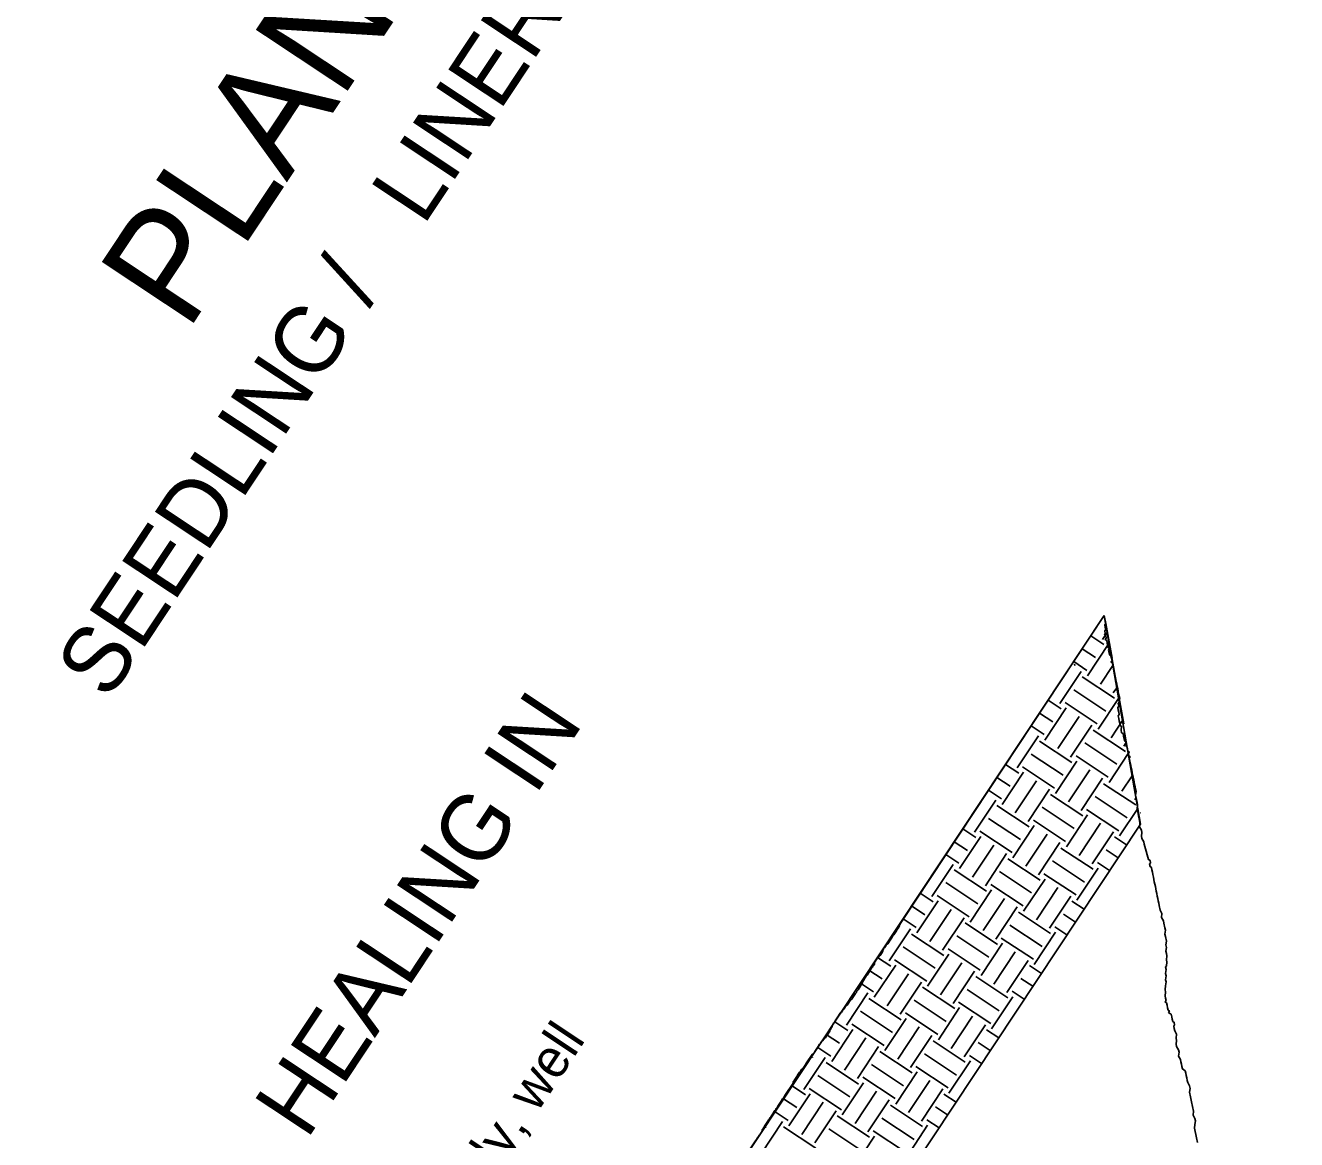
# Model space of a CAD drawing. Extents: x 561231 to 564240, y 590260 to 602519.
# Drawn here: x 563343 to 563465.5, y 590700.8 to 590808.3 of the extents above; entities that cross this region are included whole.
import ezdxf

# ---------------------------------------------------------------- set-up
doc = ezdxf.new("R2010")
doc.units = 0
doc.layers.add('Old_Level_1', color=7, linetype='Continuous')

msp = doc.modelspace()

# ---------------------------------------------------------------- linework, layer by layer
at = {"layer": 'Old_Level_1'}
for p, q in [((563410.25, 590696), (563446.98, 590751.37)), ((563446.98, 590751.37), (563448.88, 590740.92)), ((563446.98, 590751.37), (563450.47, 590731.26)), ((563447.12, 590750.62), (563447.73, 590747.26)), ((563445.68, 590749.42), (563446.95, 590748.57)), ((563446.81, 590749.08), (563447.26, 590749.75)), ((563444.86, 590748.18), (563446.13, 590747.33)), ((563445.37, 590745.57), (563447.43, 590748.67)), ((563447.33, 590749.18), (563447.36, 590749.16)), ((563444.04, 590746.94), (563445.31, 590746.09)), ((563442.7, 590742.88), (563444.75, 590745.98)), ((563444.17, 590746.57), (563444.09, 590746.7)), ((563446.61, 590744.75), (563447.81, 590746.55)), ((563444.86, 590745.46), (563447.96, 590743.41)), ((563444.04, 590744.22), (563447.14, 590742.17)), ((563446.4, 590740.43), (563448.36, 590743.39)), ((563447.85, 590743.92), (563448.18, 590744.42)), ((563441.26, 590739.37), (563443.32, 590742.47)), ((563441.57, 590743.21), (563442.84, 590742.37)), ((563443.21, 590742.98), (563446.31, 590740.93)), ((563440.75, 590741.97), (563442.02, 590741.13)), ((563442.5, 590738.54), (563444.56, 590741.65)), ((563443.74, 590737.72), (563445.8, 590740.82)), ((563447.64, 590739.6), (563448.73, 590741.26)), ((563438.58, 590736.68), (563440.64, 590739.78)), ((563439.92, 590740.73), (563441.19, 590739.89)), ((563445.92, 590740.33), (563449.02, 590738.27)), ((563440.75, 590739.26), (563443.85, 590737.21)), ((563445.1, 590739.09), (563448.2, 590737.03)), ((563448.88, 590738.78), (563449.1, 590739.12)), ((563439.92, 590738.02), (563443.02, 590735.97)), ((563442.28, 590734.23), (563444.34, 590737.33)), ((563444.27, 590737.85), (563447.37, 590735.79)), ((563447.44, 590735.27), (563449.29, 590738.06)), ((563437.15, 590733.17), (563439.21, 590736.27)), ((563437.46, 590737.01), (563438.73, 590736.17)), ((563439.1, 590736.78), (563442.2, 590734.73)), ((563443.52, 590733.4), (563445.58, 590736.5)), ((563448.68, 590734.45), (563449.66, 590735.92)), ((563436.63, 590735.77), (563437.9, 590734.93)), ((563438.39, 590732.34), (563440.45, 590735.44)), ((563444.76, 590732.58), (563446.82, 590735.68)), ((563446.92, 590735.16), (563450.03, 590733.11)), ((563434.47, 590730.48), (563436.53, 590733.58)), ((563435.81, 590734.53), (563437.08, 590733.69)), ((563439.63, 590731.52), (563441.69, 590734.62)), ((563441.8, 590734.13), (563444.91, 590732.07)), ((563446.1, 590733.92), (563449.2, 590731.87)), ((563449.92, 590733.62), (563450.03, 590733.79)), ((563436.63, 590733.06), (563439.73, 590731.01)), ((563440.98, 590732.89), (563444.08, 590730.83)), ((563445.28, 590732.68), (563448.38, 590730.63)), ((563448.46, 590730.13), (563450.21, 590732.76)), ((563450.45, 590732.35), (563450.47, 590732.34)), ((563450.47, 590731.26), (563421.94, 590688.25)), ((563435.81, 590731.82), (563438.91, 590729.77)), ((563438.17, 590728.02), (563440.23, 590731.12)), ((563440.16, 590731.65), (563443.26, 590729.59)), ((563443.33, 590729.07), (563445.38, 590732.17)), ((563444.57, 590728.25), (563446.62, 590731.35)), ((563433.04, 590726.97), (563435.09, 590730.07)), ((563433.34, 590730.81), (563434.61, 590729.97)), ((563434.99, 590730.58), (563438.09, 590728.53)), ((563439.41, 590727.2), (563441.47, 590730.3)), ((563445.81, 590727.42), (563447.86, 590730.52)), ((563447.98, 590730.03), (563449.14, 590729.26)), ((563432.52, 590729.57), (563433.79, 590728.73)), ((563434.28, 590726.14), (563436.33, 590729.24)), ((563440.65, 590726.38), (563442.71, 590729.48)), ((563442.81, 590728.96), (563445.91, 590726.91)), ((563447.16, 590728.79), (563448.32, 590728.02)), ((563430.36, 590724.28), (563432.42, 590727.38)), ((563431.7, 590728.33), (563432.97, 590727.49)), ((563435.52, 590725.32), (563437.57, 590728.42)), ((563437.69, 590727.93), (563440.79, 590725.87)), ((563441.99, 590727.72), (563445.09, 590725.67)), ((563446.34, 590727.55), (563447.5, 590726.78)), ((563432.52, 590726.86), (563435.62, 590724.81)), ((563436.87, 590726.69), (563439.97, 590724.63)), ((563441.17, 590726.48), (563444.27, 590724.43)), ((563444.35, 590723.93), (563446.41, 590727.03)), ((563431.7, 590725.62), (563434.8, 590723.57)), ((563434.06, 590721.82), (563436.11, 590724.92)), ((563436.05, 590725.45), (563439.15, 590723.39)), ((563439.21, 590722.87), (563441.27, 590725.97)), ((563440.45, 590722.04), (563442.51, 590725.14)), ((563428.92, 590720.77), (563430.98, 590723.87)), ((563429.23, 590724.61), (563430.5, 590723.77)), ((563430.87, 590724.38), (563433.97, 590722.33)), ((563435.3, 590721), (563437.35, 590724.1)), ((563441.69, 590721.22), (563443.75, 590724.32)), ((563443.87, 590723.83), (563445.03, 590723.06)), ((563428.41, 590723.37), (563429.68, 590722.53)), ((563430.16, 590719.94), (563432.22, 590723.04)), ((563436.54, 590720.18), (563438.59, 590723.28)), ((563438.7, 590722.76), (563441.8, 590720.71)), ((563443.05, 590722.59), (563444.21, 590721.82)), ((563427.58, 590722.13), (563428.85, 590721.29)), ((563431.4, 590719.12), (563433.46, 590722.22)), ((563433.58, 590721.73), (563436.68, 590719.67)), ((563437.88, 590721.52), (563440.98, 590719.47)), ((563442.23, 590721.35), (563443.39, 590720.58)), ((563426.25, 590718.08), (563428.3, 590721.18)), ((563428.41, 590720.66), (563431.51, 590718.6)), ((563432.76, 590720.49), (563435.86, 590718.43)), ((563437.05, 590720.28), (563440.15, 590718.23)), ((563440.24, 590717.72), (563442.29, 590720.83)), ((563427.58, 590719.42), (563430.68, 590717.36)), ((563431.93, 590719.25), (563435.03, 590717.19)), ((563435.1, 590716.67), (563437.16, 590719.77)), ((563436.34, 590715.84), (563438.4, 590718.94)), ((563424.81, 590714.56), (563426.87, 590717.66)), ((563425.12, 590718.41), (563426.39, 590717.57)), ((563426.76, 590718.18), (563429.86, 590716.12)), ((563429.94, 590715.62), (563432, 590718.72)), ((563431.18, 590714.8), (563433.24, 590717.9)), ((563437.58, 590715.02), (563439.64, 590718.12)), ((563439.76, 590717.63), (563440.92, 590716.86)), ((563424.29, 590717.17), (563425.56, 590716.33)), ((563426.05, 590713.74), (563428.11, 590716.84)), ((563432.42, 590713.98), (563434.48, 590717.08)), ((563434.59, 590716.56), (563437.69, 590714.51)), ((563438.93, 590716.39), (563440.1, 590715.62)), ((563423.47, 590715.93), (563424.74, 590715.09)), ((563427.29, 590712.92), (563429.35, 590716.02)), ((563429.47, 590715.53), (563432.57, 590713.47)), ((563433.76, 590715.32), (563436.86, 590713.27)), ((563438.11, 590715.15), (563439.27, 590714.38)), ((563422.13, 590711.88), (563424.19, 590714.98)), ((563424.29, 590714.46), (563427.39, 590712.4)), ((563428.64, 590714.29), (563431.74, 590712.23)), ((563432.94, 590714.08), (563436.04, 590712.03)), ((563436.12, 590711.52), (563438.18, 590714.62)), ((563423.47, 590713.22), (563426.57, 590711.16)), ((563427.82, 590713.05), (563430.92, 590710.99)), ((563430.99, 590710.47), (563433.04, 590713.57)), ((563432.23, 590709.64), (563434.28, 590712.74)), ((563420.7, 590708.36), (563422.75, 590711.46)), ((563421, 590712.21), (563422.27, 590711.37)), ((563422.65, 590711.98), (563425.75, 590709.92)), ((563425.83, 590709.42), (563427.89, 590712.52)), ((563427.07, 590708.6), (563429.13, 590711.7)), ((563433.47, 590708.82), (563435.52, 590711.92)), ((563435.64, 590711.43), (563436.81, 590710.66)), ((563420.18, 590710.97), (563421.45, 590710.13)), ((563421.94, 590707.54), (563423.99, 590710.64)), ((563428.31, 590707.78), (563430.37, 590710.88)), ((563430.47, 590710.36), (563433.57, 590708.3)), ((563434.82, 590710.19), (563435.98, 590709.42)), ((563419.36, 590709.73), (563420.63, 590708.89)), ((563423.18, 590706.72), (563425.23, 590709.82)), ((563425.35, 590709.33), (563428.45, 590707.27)), ((563429.65, 590709.12), (563432.75, 590707.06)), ((563434, 590708.95), (563435.16, 590708.18)), ((563418.02, 590705.67), (563420.08, 590708.77)), ((563418.86, 590708.73), (563418.85, 590708.75)), ((563420.18, 590708.26), (563423.28, 590706.2)), ((563424.53, 590708.09), (563427.63, 590706.03)), ((563428.83, 590707.88), (563431.93, 590705.82)), ((563432.01, 590705.32), (563434.07, 590708.42)), ((563419.36, 590707.02), (563422.46, 590704.96)), ((563423.71, 590706.85), (563426.81, 590704.79)), ((563426.87, 590704.26), (563428.93, 590707.37)), ((563428.11, 590703.44), (563430.17, 590706.54)), ((563416.58, 590702.16), (563418.64, 590705.26)), ((563416.89, 590706.01), (563418.16, 590705.17)), ((563418.53, 590705.78), (563421.64, 590703.72)), ((563421.72, 590703.22), (563423.77, 590706.32)), ((563422.96, 590702.4), (563425.01, 590705.5)), ((563429.36, 590702.62), (563431.41, 590705.72)), ((563416.07, 590704.77), (563417.34, 590703.93)), ((563417.82, 590701.34), (563419.88, 590704.44)), ((563424.2, 590701.58), (563426.25, 590704.68)), ((563426.36, 590704.16), (563429.46, 590702.1)), ((563431.53, 590705.23), (563432.69, 590704.46)), ((563415.24, 590703.53), (563416.51, 590702.69)), ((563419.06, 590700.52), (563421.12, 590703.62)), ((563421.24, 590703.13), (563424.34, 590701.07)), ((563425.54, 590702.92), (563428.64, 590700.86)), ((563430.71, 590703.99), (563431.87, 590703.22)), ((563413.91, 590699.47), (563415.96, 590702.57)), ((563414.36, 590701.96), (563414.32, 590702.03)), ((563416.07, 590702.06), (563419.17, 590700)), ((563420.42, 590701.89), (563423.52, 590699.83)), ((563424.71, 590701.68), (563427.81, 590699.62)), ((563427.9, 590699.12), (563429.95, 590702.22)), ((563429.89, 590702.75), (563431.05, 590701.98)), ((563422.76, 590698.06), (563424.82, 590701.16))]:
    msp.add_line(p, q, dxfattribs=at)
for points in [[(563446.98, 590751.37), (563427.44, 590721.83), (563427.37, 590721.73), (563427.27, 590721.58), (563427.25, 590721.44), (563427.19, 590721.34), (563427.12, 590721.24), (563427.02, 590721.09), (563426.95, 590720.98), (563426.88, 590720.88), (563426.81, 590720.78), (563426.75, 590720.68), (563426.68, 590720.58), (563426.61, 590720.48), (563426.54, 590720.37), (563426.48, 590720.27), (563426.41, 590720.17), (563426.34, 590720.07), (563426.27, 590719.97), (563426.2, 590719.86), (563426.1, 590719.71), (563425.98, 590719.64), (563425.92, 590719.54), (563425.85, 590719.44), (563425.78, 590719.34), (563425.71, 590719.23), (563425.65, 590719.13), (563425.63, 590719), (563425.56, 590718.89), (563425.49, 590718.79), (563425.43, 590718.69), (563425.36, 590718.59), (563425.29, 590718.49), (563425.17, 590718.42), (563425.1, 590718.32), (563425.04, 590718.21), (563424.97, 590718.11), (563424.9, 590718.01), (563424.83, 590717.91), (563424.82, 590717.77), (563424.75, 590717.67), (563424.68, 590717.57), (563424.62, 590717.47), (563424.55, 590717.36), (563424.48, 590717.26), (563424.41, 590717.16), (563424.34, 590717.06), (563424.28, 590716.96), (563424.18, 590716.8), (563424.11, 590716.7), (563424.04, 590716.6), (563423.97, 590716.5), (563423.9, 590716.4), (563423.84, 590716.29), (563423.77, 590716.19), (563423.7, 590716.09), (563423.68, 590715.95), (563423.62, 590715.85), (563423.55, 590715.75), (563423.48, 590715.65), (563423.41, 590715.55), (563423.35, 590715.44), (563423.25, 590715.29), (563423.14, 590715.14), (563423.08, 590715.04), (563423.01, 590714.93), (563422.94, 590714.83), (563422.87, 590714.73), (563422.81, 590714.63), (563422.74, 590714.53), (563422.67, 590714.42), (563422.52, 590714.3), (563422.42, 590714.15), (563422.32, 590714), (563422.25, 590713.9), (563422.18, 590713.79), (563422.06, 590713.73), (563421.99, 590713.62), (563421.93, 590713.52), (563421.86, 590713.42), (563421.79, 590713.32), (563421.72, 590713.22), (563421.65, 590713.11), (563421.54, 590713.05), (563421.43, 590712.89), (563421.37, 590712.79), (563421.3, 590712.69), (563421.23, 590712.59), (563421.16, 590712.49), (563421.1, 590712.38), (563421.03, 590712.28), (563420.96, 590712.18), (563420.89, 590712.08), (563420.83, 590711.98), (563420.76, 590711.87), (563420.74, 590711.74), (563420.67, 590711.64), (563420.61, 590711.53), (563420.54, 590711.43), (563420.52, 590711.3), (563420.45, 590711.19)], [(563446.98, 590751.37), (563447.12, 590750.62), (563447.03, 590750.48), (563447.07, 590750.25), (563447.12, 590750.02), (563447.03, 590749.89), (563447.08, 590749.66), (563446.99, 590749.52), (563447.12, 590749.43), (563447.17, 590749.2), (563447.08, 590749.06), (563447.22, 590748.97), (563447.26, 590748.74), (563447.31, 590748.51), (563447.35, 590748.28), (563447.49, 590748.19), (563447.4, 590748.05), (563447.45, 590747.82), (563447.49, 590747.6), (563447.63, 590747.5), (563447.68, 590747.27), (563447.73, 590747.05), (563447.63, 590746.91), (563447.77, 590746.82), (563447.82, 590746.59), (563447.86, 590746.36), (563447.91, 590746.13), (563447.96, 590745.9), (563448, 590745.67), (563448.05, 590745.44), (563448.1, 590745.21), (563448.14, 590744.98), (563448.19, 590744.76), (563448.24, 590744.53), (563448.28, 590744.3), (563448.33, 590744.07), (563448.37, 590743.84), (563448.42, 590743.61), (563448.47, 590743.38), (563448.38, 590743.24), (563448.42, 590743.01), (563448.33, 590742.88), (563448.38, 590742.65), (563448.29, 590742.51), (563448.33, 590742.28), (563448.38, 590742.05), (563448.43, 590741.82), (563448.33, 590741.69), (563448.38, 590741.46), (563448.43, 590741.23), (563448.47, 590741), (563448.52, 590740.77), (563448.66, 590740.68), (563448.61, 590740.31), (563448.66, 590740.08), (563448.8, 590739.99), (563448.84, 590739.76), (563448.89, 590739.53), (563448.94, 590739.3), (563449.07, 590739.21), (563449.12, 590738.98), (563449.03, 590738.85), (563449.17, 590738.76), (563449.21, 590738.53), (563449.26, 590738.3), (563449.4, 590738.21), (563449.31, 590738.07), (563449.35, 590737.84), (563449.49, 590737.75), (563449.4, 590737.61), (563449.45, 590737.38), (563449.49, 590737.15), (563449.54, 590736.92), (563449.59, 590736.69), (563449.63, 590736.46), (563449.68, 590736.24), (563449.72, 590736.01), (563449.77, 590735.78), (563449.82, 590735.55), (563449.91, 590735.09), (563449.96, 590734.86), (563450, 590734.63), (563450.05, 590734.4), (563450, 590734.04), (563450.05, 590733.81), (563450.14, 590733.35), (563450.19, 590733.12), (563450.15, 590732.75), (563450.19, 590732.53), (563450.24, 590732.3), (563450.28, 590732.07), (563450.38, 590731.61), (563450.42, 590731.38), (563450.38, 590731.01), (563450.56, 590730.69), (563450.61, 590730.46), (563450.56, 590730.1), (563450.61, 590729.87), (563450.79, 590729.55), (563450.84, 590729.32), (563450.89, 590729.09)], [(563450.89, 590729.09), (563451.26, 590727.85), (563451.4, 590727.76), (563451.44, 590727.53), (563451.35, 590727.4), (563451.4, 590727.17), (563451.53, 590727.08), (563451.58, 590726.85), (563451.63, 590726.62), (563451.67, 590726.39), (563451.72, 590726.16), (563451.77, 590725.93), (563451.81, 590725.7), (563451.86, 590725.47), (563451.91, 590725.24), (563451.95, 590725.01), (563452, 590724.79), (563452.05, 590724.56), (563452.09, 590724.33), (563452.14, 590724.1), (563452.19, 590723.87), (563452.23, 590723.64), (563452.28, 590723.41), (563452.37, 590722.95), (563452.55, 590722.63), (563452.51, 590722.27), (563452.69, 590721.95), (563452.74, 590721.72), (563452.83, 590721.26), (563452.88, 590721.03), (563452.83, 590720.66), (563452.88, 590720.43), (563452.97, 590719.98), (563452.93, 590719.61), (563452.98, 590719.38), (563452.93, 590719.01), (563452.98, 590718.78), (563453.02, 590718.56), (563452.98, 590718.19), (563453.03, 590717.96), (563452.98, 590717.59), (563452.89, 590717.46), (563452.94, 590717.23), (563452.89, 590716.86), (563452.94, 590716.63), (563452.89, 590716.26), (563452.94, 590716.04), (563452.89, 590715.67), (563452.85, 590715.3), (563452.9, 590715.07), (563452.85, 590714.71), (563452.9, 590714.48), (563452.94, 590714.25), (563452.85, 590714.11), (563452.99, 590714.02), (563453.04, 590713.79), (563453.08, 590713.56), (563453.13, 590713.33), (563453.27, 590713.24), (563453.18, 590713.1), (563453.31, 590713.01), (563453.45, 590712.92), (563453.5, 590712.69), (563453.54, 590712.46), (563453.59, 590712.23), (563453.73, 590712.14), (563453.77, 590711.91), (563453.68, 590711.78), (563453.73, 590711.55), (563453.78, 590711.32), (563453.96, 590711), (563453.91, 590710.63), (563453.96, 590710.4), (563453.92, 590710.03), (563453.96, 590709.81), (563454.15, 590709.49), (563454.19, 590709.26), (563454.15, 590708.89), (563454.33, 590708.57), (563454.38, 590708.34), (563454.43, 590708.11), (563454.47, 590707.88), (563454.52, 590707.65), (563454.79, 590707.47), (563454.84, 590707.24), (563454.89, 590707.01), (563454.93, 590706.78), (563454.98, 590706.55), (563455.03, 590706.33), (563455.21, 590706.01), (563455.26, 590705.78), (563455.21, 590705.41), (563455.3, 590704.95), (563455.4, 590704.49), (563455.49, 590704.04), (563455.58, 590703.58), (563455.54, 590703.21), (563455.72, 590702.89), (563455.77, 590702.66), (563455.72, 590702.29), (563455.68, 590701.93)], [(563420.45, 590711.19), (563420.39, 590711.09), (563420.32, 590710.99), (563420.25, 590710.89), (563420.18, 590710.79), (563420.12, 590710.68), (563420, 590710.62), (563419.93, 590710.51), (563419.86, 590710.41), (563419.74, 590710.34), (563419.68, 590710.24), (563419.61, 590710.14), (563419.54, 590710.04), (563419.47, 590709.94), (563419.41, 590709.83), (563419.34, 590709.73), (563419.27, 590709.63), (563419.2, 590709.53), (563419.13, 590709.43), (563419.07, 590709.32), (563419, 590709.22), (563418.93, 590709.12), (563418.81, 590709.05), (563418.75, 590708.95), (563418.68, 590708.85), (563418.61, 590708.75), (563418.54, 590708.64), (563418.47, 590708.54), (563418.41, 590708.44), (563418.34, 590708.34), (563418.27, 590708.24), (563418.2, 590708.13), (563418.14, 590708.03), (563418.07, 590707.93), (563418, 590707.83), (563417.93, 590707.73), (563417.87, 590707.62), (563417.75, 590707.56), (563417.68, 590707.45), (563417.61, 590707.35), (563417.54, 590707.25), (563417.48, 590707.15), (563417.41, 590707.05), (563417.34, 590706.94), (563417.27, 590706.84), (563417.21, 590706.74), (563417.14, 590706.64), (563417.07, 590706.54), (563417, 590706.43), (563416.99, 590706.3), (563416.92, 590706.2), (563416.85, 590706.09), (563416.78, 590705.99), (563416.72, 590705.89), (563416.65, 590705.79), (563416.58, 590705.69), (563416.51, 590705.58), (563416.45, 590705.48), (563416.38, 590705.38), (563416.31, 590705.28), (563416.24, 590705.18), (563416.17, 590705.08), (563416.11, 590704.97), (563416.04, 590704.87), (563415.97, 590704.77), (563415.9, 590704.67), (563415.84, 590704.56), (563415.77, 590704.46), (563415.7, 590704.36), (563415.63, 590704.26), (563415.57, 590704.16), (563415.5, 590704.06), (563415.43, 590703.95), (563415.36, 590703.85), (563415.3, 590703.75), (563415.23, 590703.65), (563415.16, 590703.55), (563415.09, 590703.44), (563415.02, 590703.34), (563414.96, 590703.24), (563414.89, 590703.14), (563414.82, 590703.04), (563414.75, 590702.93), (563414.69, 590702.83), (563414.62, 590702.73), (563414.55, 590702.63), (563414.48, 590702.53), (563414.42, 590702.42), (563414.35, 590702.32), (563414.28, 590702.22), (563414.21, 590702.12), (563414.15, 590702.02), (563414.08, 590701.91), (563414.01, 590701.81), (563413.99, 590701.68), (563413.93, 590701.57), (563413.86, 590701.47), (563413.79, 590701.37), (563413.72, 590701.27), (563413.66, 590701.17), (563413.55, 590701.01)], [(563455.68, 590701.93), (563455.87, 590701.01), (563455.96, 590700.55)], [(563413.55, 590701.01), (563413.45, 590700.86), (563413.38, 590700.76), (563410.25, 590696), (563410.25, 590696), (563413.35, 590700.71)]]:
    msp.add_lwpolyline(points, dxfattribs=at)

# ---------------------------------------------------------------- texts
for s, height, p in [('SEEDLING /   LINER BAREROOT PLANTING DETAIL', 6.3779, (563350.94, 590743.06)), ('PLANTING DETAILS', 10.6299, (563358.54, 590778.63)), ('HEALING IN', 6.378, (563370.09, 590700.73)), ('1.  Locate a healing-in site in a shady, well', 3.7205, (563345.35, 590632.59))]:
    msp.add_text(s, height=height, rotation=56.4424, dxfattribs=at).set_placement(p)

doc.saveas('drawing.dxf')
